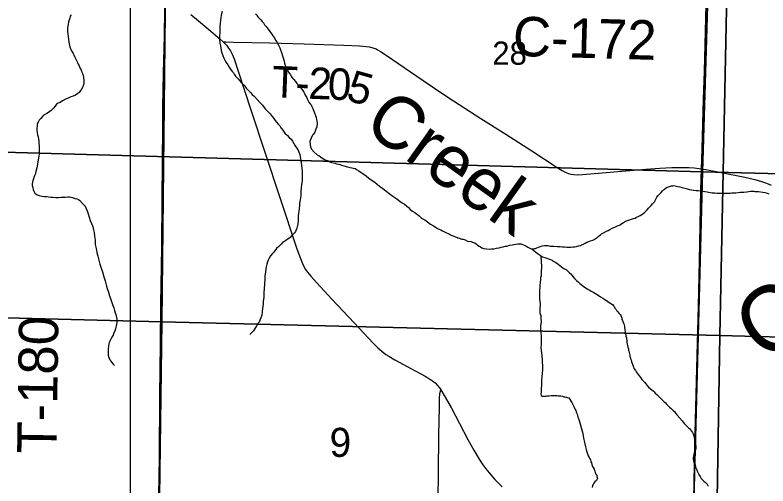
# Model space of a CAD drawing. Extents: x 0 to 68, y 0 to 52.9.
# Drawn here: x 45.735 to 47.168, y 35.989 to 36.885 of the extents above; entities that cross this region are included whole.
import ezdxf

# ---------------------------------------------------------------- set-up
doc = ezdxf.new("R2010")
doc.units = 0
for name, color, linetype in [('Default', 7, 'Continuous'), ('GM_X_County_Road', 7, 'Continuous'), ('GM_X_County_Road_Text', 7, 'Continuous'), ('GM_X_Minor_River', 7, 'Continuous'), ('GM_X_Minor_River_Text', 7, 'Continuous'), ('GM_X_State_Route', 7, 'Continuous'), ('GM_X_Township_Road', 7, 'Continuous'), ('GM_X_Township_Road_Text', 7, 'Continuous')]:
    doc.layers.add(name, color=color, linetype=linetype)

msp = doc.modelspace()

# ---------------------------------------------------------------- linework, layer by layer
at = {"layer": 'Default'}
msp.add_line((45.9541, 31.1431), (45.9541, 38.5351), dxfattribs=at)
for points in [[(45.7586, 37.9073), (45.7821, 37.907), (47.0815, 37.8719), (47.0429, 36.5865), (45.6896, 36.6248)], [(47.0815, 37.8719), (47.106, 37.8711), (48.4264, 37.8391), (48.3843, 36.5523), (47.0429, 36.5865)], [(44.9603, 37.3859), (46.0251, 37.3614), (46.0139, 36.3013), (44.9528, 36.3285)], [(46.0251, 37.3614), (47.0974, 37.332), (47.0762, 36.2748), (46.0139, 36.3013)], [(47.0974, 37.332), (48.157, 37.3036), (48.1401, 36.2463), (47.0762, 36.2748)], [(45.6896, 36.6248), (47.0429, 36.5865), (47.008, 35.2636), (45.6672, 35.3023)], [(47.0429, 36.5865), (48.3843, 36.5523), (48.3458, 35.227), (47.008, 35.2636)], [(46.0139, 36.3013), (45.9997, 35.2541), (45.9809, 35.2543), (44.9359, 35.2797), (44.9528, 36.3285)], [(47.0762, 36.2748), (47.0588, 35.2253), (47.0392, 35.2259), (45.9997, 35.2541), (46.0139, 36.3013)], [(48.1401, 36.2463), (48.1151, 35.1997), (47.0588, 35.2253), (47.0762, 36.2748)]]:
    msp.add_lwpolyline(points, close=True, dxfattribs=at)
at = {"layer": 'GM_X_County_Road'}
for points in [[(46.0084, 35.9707), (46.0092, 36.0429), (46.0101, 36.1611), (46.0112, 36.2595), (46.0121, 36.335), (46.014, 36.4433), (46.0148, 36.5353), (46.0157, 36.6732), (46.0161, 36.7093), (46.0171, 36.775), (46.0184, 36.8209), (46.0189, 36.8471), (46.0194, 36.8931), (46.0199, 36.916), (46.0201, 36.9281)], [(47.026, 35.9278), (47.0267, 35.9621), (47.0286, 36.0646), (47.0329, 36.2368), (47.0354, 36.3311), (47.0374, 36.4173), (47.0402, 36.5526), (47.0424, 36.6305), (47.045, 36.7248), (47.0467, 36.7781), (47.05, 36.9052), (47.0506, 36.9255)]]:
    msp.add_lwpolyline(points, dxfattribs=at)
at = {"layer": 'GM_X_Minor_River'}
for points in [[(46.1286, 36.8919), (46.127, 36.8849), (46.126, 36.8799), (46.1255, 36.8743), (46.125, 36.8693), (46.1245, 36.8638), (46.124, 36.8583), (46.124, 36.8513), (46.1239, 36.8448), (46.1239, 36.8382), (46.1244, 36.8317), (46.1254, 36.8267), (46.1259, 36.8217), (46.1269, 36.8172), (46.1284, 36.8131), (46.1299, 36.8081), (46.1319, 36.8031), (46.1339, 36.7991), (46.1364, 36.7946), (46.1394, 36.79), (46.1419, 36.786), (46.1444, 36.782), (46.1479, 36.7775), (46.1504, 36.7749), (46.1519, 36.7724), (46.1539, 36.7689), (46.1564, 36.7659)], [(45.8411, 36.8853), (45.8396, 36.8828), (45.8386, 36.8793), (45.8375, 36.8758), (45.8365, 36.8718), (45.8355, 36.8672), (45.835, 36.8637), (45.8345, 36.8602), (45.8345, 36.8572), (45.8345, 36.8537), (45.835, 36.8492), (45.8355, 36.8442), (45.836, 36.8392), (45.8369, 36.8331), (45.8389, 36.8246), (45.8409, 36.8191), (45.8434, 36.8151), (45.8449, 36.812), (45.8464, 36.809), (45.8479, 36.806), (45.8494, 36.8025), (45.8514, 36.7985), (45.8534, 36.7945), (45.8549, 36.7914), (45.8564, 36.7884), (45.8579, 36.7844), (45.8599, 36.7819), (45.8609, 36.7784), (45.8624, 36.7759), (45.8629, 36.7734), (45.8639, 36.7703), (45.8654, 36.7608), (45.8654, 36.7578), (45.8654, 36.7543), (45.8643, 36.7508), (45.8638, 36.7483), (45.8608, 36.7438), (45.8593, 36.7413), (45.8563, 36.7378), (45.8538, 36.7358), (45.8493, 36.7323), (45.8452, 36.7308), (45.8407, 36.7293), (45.8357, 36.7268), (45.8307, 36.7248), (45.8251, 36.7218), (45.8201, 36.7188), (45.8166, 36.7173), (45.8136, 36.7153), (45.8111, 36.7118), (45.8076, 36.7078), (45.8035, 36.7033), (45.798, 36.6993), (45.795, 36.6978), (45.7925, 36.6963), (45.788, 36.6938), (45.7859, 36.6913), (45.7834, 36.6878), (45.7804, 36.6848), (45.7784, 36.6813), (45.7769, 36.6778), (45.7764, 36.6738), (45.7759, 36.6693), (45.7758, 36.6653), (45.7763, 36.6608), (45.7773, 36.6567), (45.7783, 36.6532), (45.7793, 36.6492), (45.7798, 36.6452), (45.7798, 36.6412), (45.7803, 36.6352), (45.7803, 36.6301), (45.7803, 36.6251), (45.7803, 36.6201), (45.7798, 36.6161), (45.7792, 36.6126), (45.7757, 36.594), (45.7742, 36.5875), (45.7726, 36.5815), (45.7711, 36.5775), (45.7696, 36.5735), (45.7686, 36.57), (45.7676, 36.567), (45.7671, 36.5635), (45.7671, 36.5605)], [(46.1921, 36.887), (46.1945, 36.8845), (46.1969, 36.8817), (46.1993, 36.8788), (46.2024, 36.8756), (46.2048, 36.8727), (46.2072, 36.8699), (46.2096, 36.8666), (46.2124, 36.8634), (46.2143, 36.8609), (46.2159, 36.8585), (46.2183, 36.8553), (46.2207, 36.852), (46.2231, 36.8488), (46.225, 36.8455), (46.2282, 36.8415), (46.2302, 36.8374), (46.2325, 36.8338), (46.2373, 36.8253), (46.2388, 36.8229), (46.24, 36.8188), (46.2415, 36.8136), (46.2435, 36.8071), (46.2454, 36.8015), (46.2466, 36.797), (46.2477, 36.7934), (46.2489, 36.7894), (46.2501, 36.7865), (46.2512, 36.7841), (46.2524, 36.7821), (46.2536, 36.7789), (46.2552, 36.776), (46.2568, 36.7736), (46.2587, 36.7712), (46.2603, 36.7687), (46.2615, 36.7667), (46.2635, 36.7643), (46.2651, 36.7622), (46.2682, 36.7582), (46.271, 36.7545), (46.2738, 36.7513), (46.277, 36.7476), (46.2798, 36.7444), (46.2821, 36.7411), (46.2841, 36.7383), (46.2857, 36.7359), (46.2868, 36.7322), (46.2892, 36.7286), (46.2912, 36.7241), (46.2939, 36.7193), (46.2963, 36.716), (46.2979, 36.714), (46.2987, 36.712), (46.2999, 36.7095), (46.3014, 36.7071), (46.3022, 36.7051), (46.3034, 36.7023), (46.3046, 36.6986), (46.3065, 36.6938), (46.3077, 36.6898), (46.3084, 36.6861), (46.3092, 36.6833), (46.3099, 36.6793), (46.3087, 36.6725), (46.307, 36.6677), (46.3053, 36.6621), (46.3024, 36.6581), (46.3008, 36.6561), (46.2983, 36.6505), (46.2962, 36.6465), (46.2954, 36.6441), (46.2961, 36.6385), (46.2969, 36.634), (46.2989, 36.63), (46.3036, 36.6239), (46.3096, 36.619), (46.3128, 36.6178), (46.316, 36.6149)], [(46.1564, 36.7659), (46.1589, 36.7634), (46.1624, 36.7599), (46.1649, 36.7568), (46.1679, 36.7528), (46.1704, 36.7513), (46.1724, 36.7488), (46.1744, 36.7458), (46.1824, 36.7377), (46.1859, 36.7337), (46.1904, 36.7297), (46.1954, 36.7241), (46.2004, 36.7186), (46.2054, 36.7136), (46.2109, 36.7065), (46.2159, 36.7015), (46.2199, 36.697), (46.2239, 36.6919), (46.2269, 36.6879), (46.2299, 36.6844), (46.2324, 36.6809), (46.2354, 36.6774), (46.2384, 36.6738), (46.2409, 36.6698), (46.2444, 36.6658), (46.2479, 36.6603), (46.2529, 36.6557), (46.2564, 36.6522), (46.26, 36.6487), (46.2625, 36.6452), (46.265, 36.6406), (46.268, 36.6361), (46.2705, 36.6321), (46.2725, 36.6291), (46.274, 36.6261), (46.2754, 36.623), (46.2764, 36.6195), (46.2779, 36.6115), (46.2789, 36.6045), (46.2799, 36.598), (46.2804, 36.5934), (46.2809, 36.5879), (46.2809, 36.5829), (46.2809, 36.5774), (46.2808, 36.5694), (46.2798, 36.5623), (46.2793, 36.5563), (46.2788, 36.5493), (46.2783, 36.5408), (46.2772, 36.5332), (46.2762, 36.5267), (46.2757, 36.5222), (46.2752, 36.5167), (46.2747, 36.5112), (46.2742, 36.5072), (46.2737, 36.5027), (46.2732, 36.4991), (46.2732, 36.4961), (46.2726, 36.4871), (46.2721, 36.4841), (46.2716, 36.4816), (46.2706, 36.4791), (46.2696, 36.4761), (46.2681, 36.4731), (46.2666, 36.4706), (46.2641, 36.4676), (46.261, 36.4646), (46.258, 36.4616), (46.2535, 36.4581), (46.248, 36.4546), (46.244, 36.4526), (46.2409, 36.4491), (46.2369, 36.4446), (46.2324, 36.4406), (46.2269, 36.4336), (46.2248, 36.4311), (46.2208, 36.4266), (46.2183, 36.4221), (46.2163, 36.4186), (46.2153, 36.4151), (46.2138, 36.411), (46.2127, 36.406), (46.2117, 36.4015), (46.2112, 36.3955), (46.2102, 36.3885), (46.2097, 36.3815), (46.2092, 36.3734), (46.2086, 36.3644), (46.2081, 36.3564), (46.2081, 36.3474), (46.2071, 36.3403), (46.2066, 36.3338), (46.2055, 36.3268), (46.205, 36.3198), (46.204, 36.3138), (46.2025, 36.3088), (46.2005, 36.3042), (46.199, 36.3007), (46.1969, 36.2977), (46.1949, 36.2942), (46.1919, 36.2902)], [(46.316, 36.6149), (46.3184, 36.6133), (46.3216, 36.6116), (46.3248, 36.6092), (46.3296, 36.6079), (46.3324, 36.6063), (46.3352, 36.605), (46.3432, 36.6029), (46.3464, 36.6021), (46.3501, 36.6012), (46.3529, 36.6004), (46.3561, 36.5991), (46.3605, 36.5979), (46.3673, 36.5962), (46.3725, 36.5949), (46.3786, 36.5936), (46.3818, 36.5932), (46.3842, 36.5911), (46.3886, 36.5882), (46.3934, 36.585), (46.3982, 36.5821), (46.4029, 36.5788), (46.4077, 36.5743), (46.4145, 36.5702), (46.4193, 36.567), (46.4237, 36.5633), (46.4285, 36.5592), (46.4345, 36.5547), (46.4405, 36.5502), (46.4468, 36.5453), (46.4536, 36.54), (46.4612, 36.5351), (46.4672, 36.531), (46.4716, 36.5277), (46.476, 36.5252), (46.4796, 36.5216), (46.4832, 36.5187), (46.4867, 36.515), (46.4911, 36.5118), (46.4955, 36.5089), (46.4987, 36.5068), (46.5007, 36.5052), (46.5039, 36.5028), (46.5083, 36.4983), (46.5147, 36.495), (46.5199, 36.4913), (46.5255, 36.4872), (46.5311, 36.4835), (46.5363, 36.4806), (46.5402, 36.4778), (46.5447, 36.4761), (46.5483, 36.4741), (46.5519, 36.4724), (46.5627, 36.4674), (46.5647, 36.4662), (46.5683, 36.4645), (46.5723, 36.4629), (46.5755, 36.462), (46.5775, 36.4612), (46.5803, 36.46), (46.5831, 36.4591), (46.5851, 36.4587), (46.5875, 36.4583), (46.5911, 36.457), (46.596, 36.4549), (46.6028, 36.4537), (46.6068, 36.452), (46.6096, 36.4512), (46.612, 36.4495), (46.6148, 36.4471), (46.618, 36.445), (46.6204, 36.4438), (46.6232, 36.4421), (46.6268, 36.4409), (46.632, 36.44), (46.6381, 36.4395), (46.6417, 36.4399), (46.6441, 36.4398), (46.6465, 36.4402), (46.651, 36.4414), (46.6558, 36.4421), (46.6599, 36.4429), (46.6635, 36.4436), (46.6675, 36.4448), (46.6704, 36.4451), (46.6724, 36.4459), (46.676, 36.4467), (46.6805, 36.4474), (46.6837, 36.4482), (46.6877, 36.4489), (46.6918, 36.4493), (46.6946, 36.4492), (46.6974, 36.4492), (46.6994, 36.4488), (46.7022, 36.4475), (46.707, 36.4455), (46.7106, 36.4434), (46.7134, 36.4418), (46.7154, 36.4409), (46.7182, 36.4397), (46.7202, 36.4397)], [(45.7671, 36.5605), (45.7681, 36.5569), (45.7691, 36.5529), (45.7701, 36.5499), (45.7721, 36.5459), (45.7751, 36.5434), (45.7801, 36.5414), (45.7831, 36.5408), (45.7861, 36.5403), (45.7901, 36.5398), (45.7941, 36.5393), (45.7981, 36.5388), (45.8027, 36.5383), (45.8072, 36.5383), (45.8122, 36.5377), (45.8172, 36.5377), (45.8217, 36.5382), (45.8257, 36.5382), (45.8307, 36.5382), (45.8348, 36.5387), (45.8383, 36.5387), (45.8413, 36.5382), (45.8438, 36.5376), (45.8483, 36.5361), (45.8523, 36.5351), (45.8553, 36.5336), (45.8578, 36.5321), (45.8628, 36.5265), (45.8653, 36.524), (45.8678, 36.521), (45.8698, 36.517), (45.8718, 36.5125), (45.8738, 36.5064), (45.8758, 36.5004), (45.8778, 36.4939), (45.8828, 36.4823), (45.8838, 36.4763), (45.8848, 36.4708), (45.8858, 36.4638), (45.8867, 36.4562), (45.8872, 36.4482), (45.8887, 36.4407), (45.8902, 36.4332), (45.8922, 36.4261), (45.8937, 36.4186), (45.8962, 36.4106), (45.8982, 36.4035), (45.9007, 36.3965), (45.9036, 36.3865), (45.9061, 36.3789), (45.9081, 36.3714), (45.9101, 36.3644), (45.9121, 36.3573), (45.9141, 36.3508), (45.9166, 36.3438), (45.9186, 36.3377), (45.9206, 36.3322), (45.9226, 36.3277), (45.9241, 36.3227), (45.9251, 36.3182), (45.9266, 36.3151), (45.9271, 36.3121), (45.9275, 36.3091), (45.928, 36.3061), (45.928, 36.3031), (45.928, 36.2996), (45.9275, 36.2966), (45.927, 36.2936), (45.9265, 36.2906), (45.926, 36.2876), (45.9245, 36.2836), (45.922, 36.279), (45.921, 36.2755), (45.9189, 36.272), (45.9169, 36.268), (45.9149, 36.2645), (45.9139, 36.262), (45.9129, 36.259), (45.9124, 36.2545), (45.9119, 36.2495), (45.9119, 36.2455), (45.9118, 36.2425), (45.9118, 36.2379), (45.9133, 36.2334), (45.9148, 36.2289), (45.9208, 36.2209), (45.9238, 36.2178), (45.9238, 36.2178)], [(46.7202, 36.4397), (46.7235, 36.4404), (46.7255, 36.4408), (46.7279, 36.442), (46.7308, 36.4431), (46.7344, 36.4447), (46.7376, 36.4455), (46.7421, 36.4462), (46.7461, 36.4461), (46.7489, 36.4461), (46.7533, 36.4452), (46.7598, 36.4448), (46.7666, 36.4443), (46.7719, 36.4442), (46.7763, 36.4437), (46.7807, 36.4437), (46.7847, 36.4432), (46.7888, 36.4432), (46.7924, 36.4431), (46.796, 36.4435), (46.8001, 36.4438), (46.8033, 36.4446), (46.8069, 36.4458), (46.8106, 36.4465), (46.813, 36.4473), (46.8154, 36.4485), (46.8195, 36.4508), (46.8231, 36.4524), (46.8268, 36.4539), (46.83, 36.4551), (46.8341, 36.4566), (46.8369, 36.4578), (46.8389, 36.459), (46.8426, 36.4614), (46.8446, 36.4633), (46.8466, 36.4649), (46.8487, 36.4669), (46.8511, 36.4685), (46.8532, 36.4697), (46.8613, 36.474), (46.8633, 36.4751), (46.8665, 36.4771), (46.871, 36.4795), (46.8759, 36.4814), (46.8799, 36.483), (46.8827, 36.4841), (46.8848, 36.4849), (46.8872, 36.4865), (46.8896, 36.4881), (46.8925, 36.49), (46.8965, 36.4924), (46.9002, 36.494), (46.9042, 36.4955), (46.9079, 36.4967), (46.9115, 36.4978), (46.9147, 36.4986), (46.9176, 36.5002), (46.9208, 36.5017), (46.9245, 36.5037), (46.9273, 36.5052), (46.9294, 36.5068), (46.9334, 36.51), (46.9359, 36.5124), (46.9379, 36.5144), (46.94, 36.5171), (46.9428, 36.5199), (46.9453, 36.5223), (46.9477, 36.5255), (46.9498, 36.5275), (46.9514, 36.5294), (46.953, 36.5318), (46.9543, 36.5346), (46.9559, 36.5382), (46.9588, 36.5414), (46.9612, 36.5442), (46.9641, 36.547), (46.967, 36.5505), (46.969, 36.5521), (46.971, 36.5533), (46.9747, 36.5565), (46.982, 36.5592), (46.984, 36.56), (46.9864, 36.5599), (46.9888, 36.5603), (46.9912, 36.5599), (46.9933, 36.5594), (46.9961, 36.5586), (47.0001, 36.5577), (47.0041, 36.5569), (47.0069, 36.556), (47.0097, 36.5556), (47.0121, 36.5548), (47.0145, 36.5539), (47.0181, 36.5527), (47.0222, 36.5522), (47.0262, 36.5514), (47.031, 36.5513), (47.0346, 36.5509), (47.0387, 36.5504), (47.0427, 36.5495), (47.0475, 36.5491)], [(47.0475, 36.5491), (47.0519, 36.5482), (47.0547, 36.5478), (47.0576, 36.5473), (47.0612, 36.5469), (47.064, 36.5464), (47.0664, 36.5464), (47.0712, 36.546), (47.0761, 36.5459), (47.0801, 36.5458), (47.0845, 36.5462), (47.089, 36.5461), (47.093, 36.5461), (47.0962, 36.546), (47.099, 36.5464), (47.1019, 36.5468), (47.1063, 36.5467), (47.1107, 36.547), (47.1148, 36.5478), (47.1216, 36.5481), (47.1269, 36.5488), (47.1313, 36.5492), (47.1349, 36.5495), (47.1382, 36.5495), (47.1406, 36.5499), (47.143, 36.5494), (47.1458, 36.5494), (47.1498, 36.5489), (47.1579, 36.548), (47.1615, 36.5472), (47.1659, 36.5459), (47.1695, 36.5447)], [(46.7182, 36.4397), (46.729, 36.4311), (46.7302, 36.4307), (46.7322, 36.4295), (46.7354, 36.4266), (46.7386, 36.425), (46.743, 36.4237), (46.7466, 36.4224), (46.7502, 36.4212), (46.7538, 36.4199), (46.757, 36.4183), (46.7602, 36.4162), (46.763, 36.4146), (46.7658, 36.4125), (46.7682, 36.4109), (46.7718, 36.408), (46.7746, 36.4056), (46.7774, 36.4039), (46.7794, 36.4027), (46.7818, 36.4011), (46.7842, 36.3998), (46.7874, 36.397), (46.7902, 36.3941), (46.7922, 36.3921), (46.7945, 36.3897), (46.7969, 36.3868), (46.7997, 36.3836), (46.8017, 36.3811), (46.8041, 36.3791), (46.8061, 36.3775), (46.8096, 36.3738), (46.812, 36.3718), (46.8148, 36.3701), (46.8176, 36.3677), (46.8204, 36.366), (46.8228, 36.3644), (46.8252, 36.3627), (46.8284, 36.3611), (46.8312, 36.3594), (46.8336, 36.3582), (46.836, 36.357), (46.8444, 36.3516), (46.8488, 36.3488), (46.8532, 36.3459), (46.8572, 36.3434), (46.8604, 36.3418), (46.8628, 36.3397), (46.8652, 36.3381), (46.8688, 36.3357), (46.8716, 36.334), (46.8744, 36.3308), (46.8771, 36.3263), (46.8787, 36.3243), (46.8803, 36.3222), (46.8819, 36.3202), (46.8835, 36.3178), (46.8862, 36.3149), (46.8874, 36.3129), (46.8886, 36.3101), (46.8894, 36.3081), (46.8898, 36.3056), (46.8909, 36.3036), (46.8917, 36.3016), (46.8925, 36.2988), (46.8937, 36.2959), (46.8944, 36.2923), (46.8948, 36.2895), (46.8952, 36.2863), (46.8959, 36.2815), (46.8967, 36.2782), (46.897, 36.2758), (46.8974, 36.2738), (46.8986, 36.2706), (46.8986, 36.2686), (46.8989, 36.2657), (46.8993, 36.2617), (46.9012, 36.2529), (46.9019, 36.2496), (46.9023, 36.2472), (46.9027, 36.2452), (46.9035, 36.2428), (46.9038, 36.24), (46.9046, 36.2379), (46.905, 36.2359), (46.9054, 36.2335), (46.9065, 36.2291), (46.9077, 36.2267), (46.9081, 36.2246), (46.91, 36.2202), (46.9112, 36.2166), (46.9131, 36.2117), (46.9155, 36.2085), (46.9171, 36.206), (46.9187, 36.2036), (46.9203, 36.2008), (46.9222, 36.1983), (46.9254, 36.1943), (46.9278, 36.1914), (46.9302, 36.189), (46.9326, 36.1861), (46.9349, 36.1833)], [(46.7354, 36.4266), (46.7367, 36.4057), (46.7362, 36.3961), (46.7357, 36.3888), (46.7349, 36.3856), (46.7348, 36.3824), (46.7339, 36.3768), (46.7335, 36.3704), (46.7329, 36.3575), (46.7328, 36.3519), (46.7331, 36.3447), (46.7335, 36.3394), (46.7338, 36.3358), (46.7338, 36.3322), (46.7337, 36.3278), (46.7333, 36.323), (46.7332, 36.3202), (46.7332, 36.3181), (46.734, 36.3149), (46.7352, 36.3129), (46.7355, 36.3105), (46.7355, 36.3081), (46.7355, 36.3061), (46.7358, 36.302), (46.7354, 36.2972), (46.7349, 36.2928), (46.7344, 36.2876), (46.7348, 36.2848), (46.7352, 36.2816), (46.7359, 36.2723), (46.7357, 36.2578), (46.7356, 36.2518), (46.7359, 36.2462), (46.737, 36.2369), (46.7377, 36.2285), (46.7381, 36.2229), (46.7384, 36.2192), (46.7388, 36.2164), (46.7388, 36.2144), (46.7383, 36.2096), (46.7378, 36.2032), (46.7373, 36.1963), (46.7368, 36.1903), (46.7368, 36.1863), (46.7368, 36.1835), (46.7363, 36.1811), (46.7363, 36.1791), (46.7362, 36.1747), (46.7361, 36.167), (46.7353, 36.1642), (46.7357, 36.1606), (46.7381, 36.1598), (46.7401, 36.1593), (46.7433, 36.1593), (46.7457, 36.1597), (46.7477, 36.16), (46.7514, 36.1604), (46.755, 36.1608), (46.7574, 36.1607), (46.7598, 36.1607), (46.7618, 36.1607), (46.7659, 36.1606), (46.7683, 36.1602), (46.7703, 36.1602), (46.7731, 36.1601), (46.7767, 36.1593), (46.7791, 36.1584), (46.7815, 36.158), (46.7844, 36.1576), (46.7864, 36.1571), (46.7888, 36.1567), (46.7943, 36.1478), (46.7963, 36.1437), (46.7978, 36.1409), (46.799, 36.1385), (46.8006, 36.1344), (46.8018, 36.1324), (46.8025, 36.13), (46.8033, 36.128), (46.8045, 36.1251), (46.8053, 36.1227), (46.806, 36.1199), (46.8072, 36.1171), (46.8084, 36.113), (46.8095, 36.109), (46.8111, 36.1042), (46.8126, 36.0977), (46.8142, 36.0929), (46.8153, 36.0888), (46.8161, 36.0848), (46.8168, 36.0796), (46.818, 36.0743), (46.8191, 36.0691), (46.8202, 36.0631), (46.8218, 36.0582), (46.8229, 36.0538), (46.8241, 36.0498), (46.8253, 36.0461), (46.8272, 36.0429), (46.8284, 36.0405), (46.8296, 36.0384)], [(46.1919, 36.2902), (46.1884, 36.2842), (46.1854, 36.2807), (46.1818, 36.2777), (46.1818, 36.2772)], [(46.9349, 36.1833), (46.9373, 36.1805), (46.9405, 36.1764), (46.9441, 36.1735), (46.9469, 36.1719), (46.9489, 36.1699), (46.9509, 36.1678), (46.9528, 36.165), (46.956, 36.1629), (46.9584, 36.1601), (46.9612, 36.1576), (46.9644, 36.1544), (46.9676, 36.1515), (46.9704, 36.1487), (46.9728, 36.1466), (46.9747, 36.1442), (46.9775, 36.1414), (46.9803, 36.1389), (46.9827, 36.1369), (46.9851, 36.134), (46.9875, 36.132), (46.9895, 36.1304), (46.9914, 36.1275), (46.9946, 36.1235), (47.0042, 36.1129), (47.0065, 36.11), (47.0089, 36.1072), (47.0121, 36.1039), (47.0145, 36.1015), (47.0165, 36.0995), (47.0185, 36.0978), (47.0204, 36.0954), (47.022, 36.093), (47.024, 36.0901), (47.0252, 36.0881), (47.026, 36.0861), (47.0263, 36.0841), (47.0275, 36.0812), (47.0283, 36.0764), (47.0294, 36.0724), (47.0298, 36.0684), (47.0305, 36.0647), (47.0305, 36.0627), (47.0301, 36.0599), (47.0296, 36.0575), (47.0288, 36.0555), (47.028, 36.0535), (47.0275, 36.0515), (47.0267, 36.0483), (47.0259, 36.0451), (47.0254, 36.0427), (47.0254, 36.0395), (47.0257, 36.0363), (47.0265, 36.0334), (47.0277, 36.031), (47.0289, 36.0286), (47.03, 36.0246), (47.032, 36.0193), (47.0335, 36.0157), (47.0347, 36.0128), (47.0363, 36.0104), (47.0375, 36.0084), (47.0387, 36.0064), (47.0406, 36.0031), (47.0426, 36.0007), (47.0454, 35.9978), (47.0486, 35.995), (47.0522, 35.9921), (47.0541, 35.9885)], [(46.8296, 36.0384), (46.8308, 36.0348), (46.8315, 36.0324), (46.8327, 36.0296), (46.8339, 36.0259), (46.835, 36.0235), (46.8366, 36.0203), (46.8382, 36.017), (46.839, 36.0142), (46.8401, 36.0114), (46.8417, 36.0089), (46.8421, 36.0065), (46.8432, 36.0029), (46.8416, 35.9993), (46.8383, 35.9965), (46.8363, 35.9941), (46.835, 35.9913), (46.8338, 35.9894), (46.833, 35.9858)]]:
    msp.add_lwpolyline(points, dxfattribs=at)
at = {"layer": 'GM_X_State_Route'}
msp.add_lwpolyline([(46.0693, 36.8862), (46.0798, 36.8771), (46.1031, 36.8572), (46.1252, 36.839), (46.1305, 36.8342), (46.137, 36.8275), (46.1411, 36.8222), (46.1448, 36.8166), (46.1477, 36.8107), (46.1514, 36.8015), (46.1598, 36.7765), (46.1833, 36.7048), (46.238, 36.5396), (46.271, 36.4398), (46.2777, 36.4213), (46.2814, 36.4123), (46.2844, 36.4064), (46.2876, 36.4008), (46.2913, 36.3955), (46.2973, 36.3878), (46.3082, 36.3756), (46.3374, 36.3444), (46.3801, 36.2989), (46.4159, 36.2605), (46.4252, 36.2513), (46.4326, 36.2449), (46.4404, 36.239), (46.4458, 36.2354), (46.4572, 36.2289), (46.489, 36.2118), (46.5151, 36.1978), (46.5236, 36.1928), (46.529, 36.1889), (46.5341, 36.1847), (46.5388, 36.18), (46.5429, 36.1748), (46.5453, 36.1713), (46.5533, 36.1579), (46.5644, 36.1377), (46.5966, 36.0768), (46.6077, 36.0567), (46.6179, 36.0398), (46.6251, 36.0289), (46.6309, 36.021), (46.6371, 36.0134), (46.6479, 36.0012), (46.6616, 35.987)], dxfattribs=at)
at = {"layer": 'GM_X_Township_Road'}
for points in [[(46.1305, 36.8342), (46.1356, 36.8339), (46.1506, 36.8333), (46.2195, 36.8323), (46.2851, 36.8304), (46.3606, 36.8276), (46.3901, 36.8263), (46.4031, 36.8254), (46.4095, 36.8244), (46.4157, 36.8228), (46.4217, 36.8205), (46.4246, 36.819), (46.4303, 36.8158), (46.4412, 36.8087), (46.5115, 36.7603), (46.5468, 36.7362), (46.5689, 36.722), (46.6213, 36.6883), (46.6685, 36.6584), (46.7182, 36.6265), (46.7648, 36.5959), (46.776, 36.5888), (46.7819, 36.5858), (46.7881, 36.5834), (46.7926, 36.5823), (46.7979, 36.5815), (46.8045, 36.5811), (46.8144, 36.5815), (46.8897, 36.5878), (46.9355, 36.5918), (46.9616, 36.5938), (46.9846, 36.5948), (47.0075, 36.5951), (47.0173, 36.5949), (47.0271, 36.5942), (47.0368, 36.5931), (47.0497, 36.591), (47.0788, 36.5856), (47.1238, 36.5764), (47.1429, 36.5718), (47.1555, 36.5682), (47.1647, 36.5651), (47.1737, 36.5613)], [(46.5297, 35.2411), (46.5314, 35.4187), (46.5322, 35.4614), (46.5329, 35.5074), (46.5337, 35.5502), (46.5343, 35.5896), (46.5349, 35.6191), (46.5362, 35.7176), (46.5371, 35.7737), (46.538, 35.8251), (46.5385, 35.8825), (46.5398, 35.9645), (46.5405, 36.0132), (46.5414, 36.0862), (46.5424, 36.1384), (46.5424, 36.157), (46.543, 36.1618), (46.5434, 36.1648), (46.5453, 36.1713)]]:
    msp.add_lwpolyline(points, dxfattribs=at)

# ---------------------------------------------------------------- texts
at = {"layer": 'Default'}
for s, height, p in [('28', 0.0442, (46.643, 36.7904)), ('9', 0.0553, (46.3332, 36.044))]:
    msp.add_text(s, height=height, rotation=0, dxfattribs=at).set_placement(p)
at = {"layer": 'GM_X_County_Road_Text'}
msp.add_text('C-172', height=0.075, rotation=358.3476, dxfattribs=at).set_placement((46.6814, 36.8074))
at = {"layer": 'GM_X_Minor_River_Text'}
for height, rotation, p in [(0.10004, 324.5413, (46.3942, 36.6685)), (0.12505, 35.8788, (47.1629, 36.2201))]:
    msp.add_text('Creek', height=height, rotation=rotation, dxfattribs=at).set_placement(p)
at = {"layer": 'GM_X_Township_Road_Text'}
for s, height, rotation, p in [('T', 0.06, 357.758, (46.2226, 36.7285)), ('2', 0.06, 357.7647, (46.2921, 36.7258)), ('0', 0.06, 357.7802, (46.329, 36.7243)), ('5', 0.06, 344.4049, (46.3623, 36.7235)), ('-', 0.06, 357.7621, (46.2675, 36.7267)), ('T-180', 0.075, 89.1554, (45.8133, 36.0497))]:
    msp.add_text(s, height=height, rotation=rotation, dxfattribs=at).set_placement(p)

doc.saveas('drawing.dxf')
